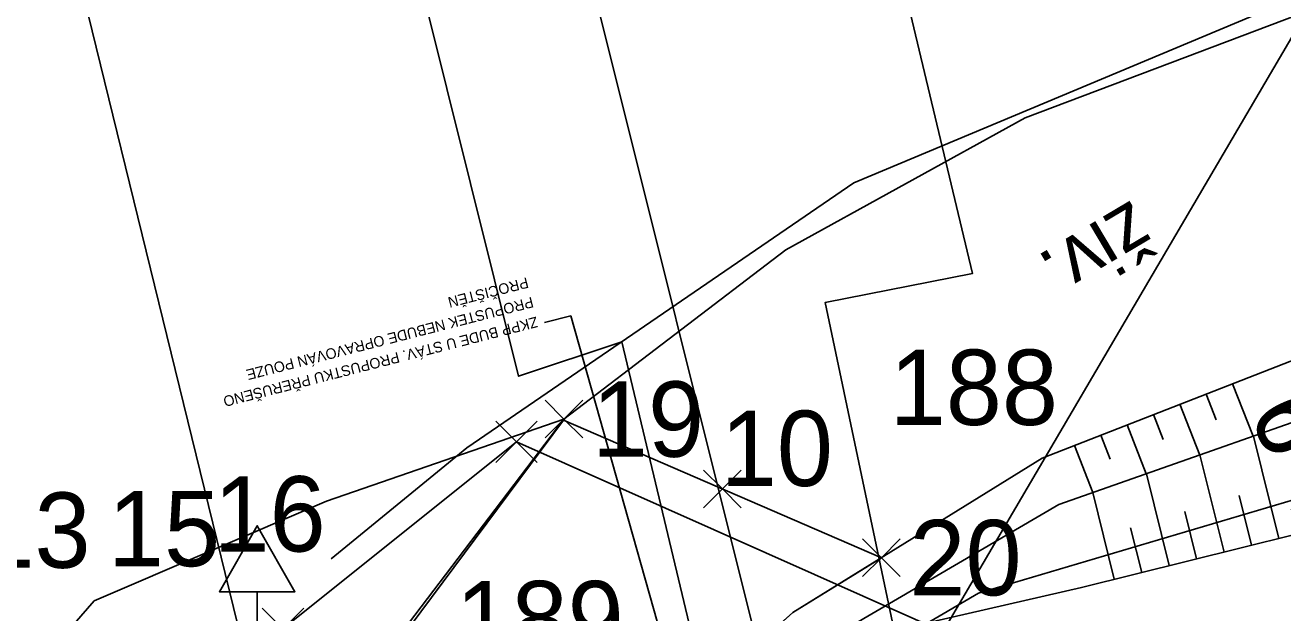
# Model space of a CAD drawing. Extents: x -806456 to -805395, y -1150847 to -1150506.
# Drawn here: x -806177.4 to -806144.04, y -1150698.35 to -1150682.75 of the extents above; entities that cross this region are included whole.
import ezdxf

# ---------------------------------------------------------------- set-up
doc = ezdxf.new("R2010")
doc.units = 0
for name, color, linetype in [('0-Kóty_a_šrafy_hranice', 7, 'Continuous'), ('0-Trativody+svodna_potrubi', 7, 'Continuous'), ('0381KM032-037P - Vrstva 17', 7, 'Continuous'), ('0381KM032-037P - Vrstva 19', 7, 'Continuous'), ('0381KM032-037P - Vrstva 3', 7, 'Continuous'), ('0381KM032-037P - Vrstva 4', 7, 'Continuous'), ('0381KM032-037P - Vrstva 48', 7, 'Continuous'), ('0381KM032-037P - Vrstva 49', 7, 'Continuous'), ('0381KM032-037P - Vrstva 51', 7, 'Continuous'), ('0381KM032-037P - Vrstva 7', 7, 'Continuous'), ('Default', 7, 'Continuous'), ('hran DP - hran DP', 7, 'Continuous'), ('lomové body', 7, 'Continuous'), ('PSR_C2_2_Lomove_body_Vimperk - Vrstva 60', 7, 'Continuous'), ('PSR_C2_2_trasa_Vimperk - Kabelová trasa', 7, 'Continuous')]:
    doc.layers.add(name, color=color, linetype=linetype)

msp = doc.modelspace()

# ---------------------------------------------------------------- linework, layer by layer
at = {"layer": '0-Kóty_a_šrafy_hranice'}
msp.add_lwpolyline([(-806173.315, -1150706.94), (-806163.12, -1150693.238), (-806154.686, -1150696.886), (-806157.039, -1150698.345), (-806159.431, -1150700.487), (-806160.936, -1150702.054), (-806162.648, -1150704.154)], close=True, dxfattribs=at)
at = {"layer": '0-Trativody+svodna_potrubi'}
msp.add_line((-806162.923, -1150690.466), (-806163.621, -1150690.644), dxfattribs=at)
msp.add_lwpolyline([(-806159.31, -1150703.279), (-806162.923, -1150690.466)], dxfattribs=at)
at = {"layer": '0381KM032-037P - Vrstva 17'}
msp.add_lwpolyline([(-806169.284, -1150696.914), (-806165.684, -1150693.969), (-806155.413, -1150686.939), (-806141.029, -1150680.901), (-806121.846, -1150675.136), (-806106.33, -1150670.053), (-806095.392, -1150665.453)], dxfattribs=at)
at = {"layer": '0381KM032-037P - Vrstva 19'}
msp.add_line((-806157.446, -1150701.329), (-806169.593, -1150652.631), dxfattribs=at)
at = {"layer": '0381KM032-037P - Vrstva 3'}
msp.add_lwpolyline([(-806158.28, -1150704.94), (-806161.571, -1150691.159), (-806164.309, -1150692.072), (-806173.835, -1150653.806)], dxfattribs=at)
at = {"layer": '0381KM032-037P - Vrstva 4'}
msp.add_line((-806169.501, -1150707.868), (-806182.162, -1150656.159), dxfattribs=at)
at = {"layer": '0381KM032-037P - Vrstva 48'}
for p, q in [((-806146.071, -1150692.543), (-806145.803, -1150693.227)), ((-806145.372, -1150692.27), (-806144.828, -1150693.662)), ((-806146.769, -1150692.815), (-806146.244, -1150694.161)), ((-806147.468, -1150693.088), (-806147.21, -1150693.749)), ((-806148.167, -1150693.361), (-806147.66, -1150694.659)), ((-806149.564, -1150693.907), (-806149.076, -1150695.157)), ((-806148.865, -1150693.634), (-806148.616, -1150694.271)), ((-806144.143, -1150696.376), (-806144.817, -1150693.658)), ((-806145.599, -1150696.737), (-806146.238, -1150694.159)), ((-806147.054, -1150697.098), (-806147.659, -1150694.659)), ((-806148.51, -1150697.459), (-806149.081, -1150695.159)), ((-806144.871, -1150696.557), (-806145.199, -1150695.233)), ((-806146.327, -1150696.918), (-806146.638, -1150695.663)), ((-806147.782, -1150697.279), (-806148.076, -1150696.094))]:
    msp.add_line(p, q, dxfattribs=at)
at = {"layer": '0381KM032-037P - Vrstva 49'}
for points in [[(-806106.833, -1150681.791), (-806120.865, -1150686.009), (-806130.84, -1150689.204), (-806140.721, -1150692.217), (-806149.976, -1150695.474), (-806155.41, -1150698.652)], [(-806160.94, -1150702.044), (-806159.44, -1150700.497), (-806157.039, -1150698.345), (-806150.424, -1150694.243), (-806141.479, -1150690.749), (-806131.125, -1150687.358), (-806121.483, -1150684.155)], [(-806155.863, -1150700.934), (-806155.366, -1150700.637), (-806154.958, -1150699.45), (-806154.576, -1150699.231), (-806153.885, -1150698.711), (-806149.376, -1150697.674), (-806139.489, -1150695.222), (-806130.934, -1150692.921), (-806118.589, -1150689.919), (-806108.264, -1150688.165)], [(-806157.224, -1150688.717), (-806163.106, -1150693.208), (-806169.402, -1150695.384), (-806175.562, -1150698.028), (-806181.812, -1150705.214), (-806196.093, -1150709.847), (-806203.772, -1150712.233), (-806204.393, -1150713.538)]]:
    msp.add_lwpolyline(points, dxfattribs=at)
at = {"layer": '0381KM032-037P - Vrstva 51'}
for points in [[(-806195.218, -1150723.443), (-806183.651, -1150718.077), (-806179.484, -1150714.678), (-806176.794, -1150711.837), (-806173.358, -1150707), (-806168.375, -1150700.145), (-806163.106, -1150693.208), (-806157.224, -1150688.717), (-806150.874, -1150685.207), (-806140.159, -1150681.153)], [(-806194.182, -1150731.583), (-806186.226, -1150728.982), (-806178.594, -1150724.924), (-806174.208, -1150722.043), (-806171.128, -1150719.056), (-806168.37, -1150714.464), (-806165.452, -1150708.868), (-806162.708, -1150704.236), (-806160.94, -1150702.044), (-806159.44, -1150700.497), (-806157.039, -1150698.345), (-806150.424, -1150694.243), (-806141.479, -1150690.749), (-806131.125, -1150687.358), (-806121.483, -1150684.155)], [(-806171.242, -1150699.79), (-806171.242, -1150697.79), (-806170.242, -1150697.79), (-806171.242, -1150696.04), (-806172.242, -1150697.79), (-806171.242, -1150697.79)]]:
    msp.add_lwpolyline(points, dxfattribs=at)
at = {"layer": '0381KM032-037P - Vrstva 7'}
msp.add_lwpolyline([(-806154.215, -1150699.444), (-806156.181, -1150690.115), (-806152.272, -1150689.343), (-806161.508, -1150650.617)], dxfattribs=at)
at = {"layer": 'Default'}
msp.add_lwpolyline([(-806156.561, -1150704.831), (-806142.158, -1150680.251), (-806127.056, -1150679.769)], dxfattribs=at)
at = {"layer": 'hran DP - hran DP'}
for p, q in [((-806152.11, -1150697.83), (-806107.35, -1150684.54)), ((-806161.05, -1150703.03), (-806152.11, -1150697.83))]:
    msp.add_line(p, q, dxfattribs=at)
at = {"layer": 'lomové body'}
for p, q in [((-806163.106, -1150693.208), (-806163.606, -1150692.708)), ((-806163.106, -1150693.208), (-806162.606, -1150692.708)), ((-806163.106, -1150693.208), (-806163.606, -1150693.708)), ((-806163.106, -1150693.208), (-806162.606, -1150693.708)), ((-806158.903, -1150695.062), (-806159.403, -1150694.562)), ((-806158.903, -1150695.062), (-806158.403, -1150694.562)), ((-806158.903, -1150695.062), (-806159.403, -1150695.562)), ((-806158.903, -1150695.062), (-806158.403, -1150695.562)), ((-806154.686, -1150696.886), (-806155.186, -1150696.386)), ((-806154.686, -1150696.886), (-806154.186, -1150696.386)), ((-806154.686, -1150696.886), (-806155.186, -1150697.386)), ((-806154.686, -1150696.886), (-806154.186, -1150697.386))]:
    msp.add_line(p, q, dxfattribs=at)
at = {"layer": 'PSR_C2_2_Lomove_body_Vimperk - Vrstva 60'}
for p, q in [((-806164.914, -1150694.362), (-806163.814, -1150693.262)), ((-806163.814, -1150694.362), (-806164.914, -1150693.262)), ((-806171.108, -1150699.325), (-806170.008, -1150698.225)), ((-806170.008, -1150699.325), (-806171.108, -1150698.225))]:
    msp.add_line(p, q, dxfattribs=at)
at = {"layer": 'PSR_C2_2_trasa_Vimperk - Kabelová trasa'}
msp.add_lwpolyline([(-806152.506, -1150699.09), (-806164.364, -1150693.812), (-806170.559, -1150698.775)], dxfattribs=at)

# ---------------------------------------------------------------- texts
at = {"layer": '0-Trativody+svodna_potrubi'}
for s, p in [('PROČIŠTĚN', (-806164.09, -1150689.441)), ('PROPUSTEK NEBUDE OPRAVOVÁN POUZE', (-806163.957, -1150689.96)), ('ZKPP BUDE U STÁV. PROPUSTKU PŘERUŠENO', (-806163.841, -1150690.485))]:
    msp.add_text(s, height=0.28, rotation=194.3488, dxfattribs=at).set_placement(p)
at = {"layer": '0381KM032-037P - Vrstva 48'}
msp.add_text('1,9', height=2, rotation=113.3162, dxfattribs=at).set_placement((-806141.64, -1150695.644))
at = {"layer": '0381KM032-037P - Vrstva 51'}
msp.add_text('živ.', height=1.5, rotation=210.724, dxfattribs=at).set_placement((-806148.035, -1150687.371))
at = {"layer": 'Default'}
for s, p in [('188', (-806154.465, -1150693.364)), ('189', (-806165.981, -1150699.504))]:
    msp.add_text(s, height=2, dxfattribs=at).set_placement(p)
at = {"layer": 'lomové body'}
for s, p in [(' 19', (-806163.106, -1150694.208)), (' 10', (-806159.69, -1150694.983)), (' 16', (-806173.143, -1150696.723)), (' 13', (-806179.378, -1150697.155)), (' 15', (-806175.943, -1150697.112)), (' 20', (-806154.686, -1150697.886))]:
    msp.add_text(s, height=2, dxfattribs=at).set_placement(p)

doc.saveas('drawing.dxf')
